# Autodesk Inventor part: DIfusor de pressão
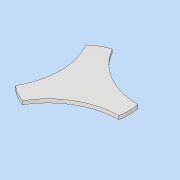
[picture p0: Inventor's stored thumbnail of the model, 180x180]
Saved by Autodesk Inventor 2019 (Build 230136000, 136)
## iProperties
Created: 2019-08
Part Number: DIfusor de pressão
Material: Plástico PPS
Document SubType Name: Modeling
Designer: Usuario
Density: 1.637 g/cm^3
Appearance: Liso - Branco
Author: Usuario
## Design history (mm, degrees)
sketch "Esboço1"
  geometry: A1 r 14.617 centre (-9.594, -16.617) between (3.065, -9.308) and (-9.594, -2); A2 r 14.617 centre (19.187, 0) between (6.529, 7.308) and (6.529, -7.308); A3 r 14.617 centre (-9.594, 16.617) between (-9.594, 2) and (3.065, 9.308); A4 r 9.8 centre (0, 0) between (3.065, -9.308) and (6.529, -7.308); A5 r 9.8 centre (0, 0) between (6.529, 7.308) and (3.065, 9.308); A6 r 9.8 centre (0, 0) between (-9.594, 2) and (-9.594, -2); 1 further point
  constraints: 12 point on circle, 6 centre point, 1 coincident, 13 other
  dimensions: "d7" = 360 deg dimension on point (0, 0) A1.centre (derived)
extrude "Extrusão1" new body sketch "Esboço1" distance "d9" = 0.75; taper "d10" = 0 deg
node "Sólido1"
other parameters: "d0" = 19.6
